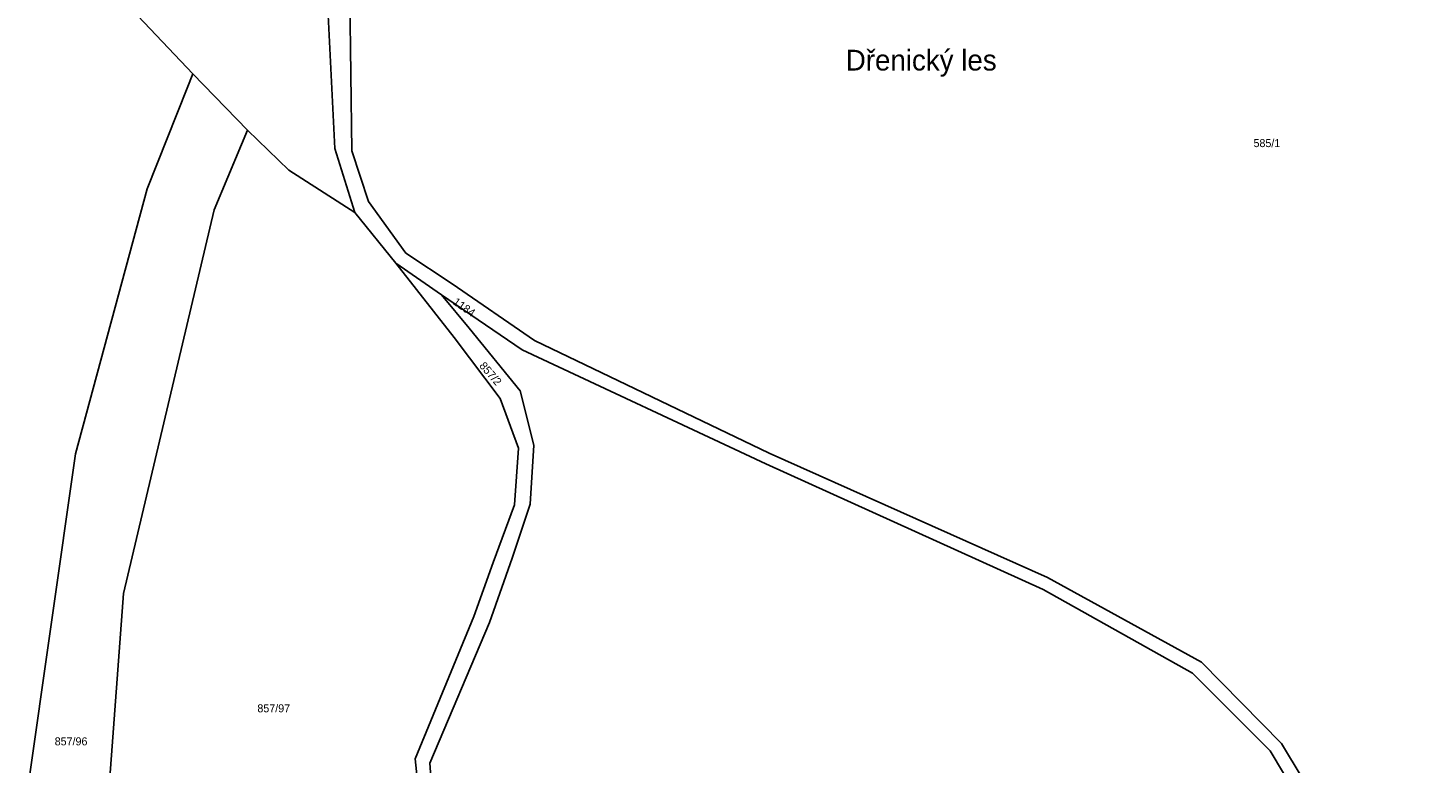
# Model space of a CAD drawing. Extents: x -887272 to -877616, y -1026687 to -1019819.
# Drawn here: x -884977.6 to -884684.7, y -1024492.3 to -1024336 of the extents above; entities that cross this region are included whole.
import ezdxf

# ---------------------------------------------------------------- set-up
doc = ezdxf.new("R2010")
doc.units = 0
for name, color, linetype in [('Hranice parcel', 7, 'Continuous'), ('Parcelní čísla', 7, 'Continuous'), ('Pop  PČ popisy', 7, 'Continuous')]:
    doc.layers.add(name, color=color, linetype=linetype)

msp = doc.modelspace()

# ---------------------------------------------------------------- linework, layer by layer
at = {"layer": 'Hranice parcel'}
for p, q in [((-884942.46, -1024345.79), (-884930.86, -1024357.79)), ((-884908.06, -1024375.26), (-884899.36, -1024386)), ((-884889.62, -1024392.74), (-884899.36, -1024386))]:
    msp.add_line(p, q, dxfattribs=at)
for points in [[(-884867, -1024267.34), (-884875.02, -1024271.26), (-884886.68, -1024276.28), (-884897.76, -1024288.38), (-884904.78, -1024302.7), (-884909.14, -1024329.5), (-884908.7, -1024362.16), (-884905.12, -1024372.96), (-884897.2, -1024383.94), (-884887.36, -1024390.42), (-884869.88, -1024402.44), (-884820.08, -1024426.42), (-884760.96, -1024452.82), (-884728.26, -1024470.78), (-884711.24, -1024488.02), (-884684.7, -1024532.14), (-884687.32, -1024533.72), (-884713.62, -1024489.62), (-884730.14, -1024473.14), (-884761.82, -1024455.36), (-884820.76, -1024428.66), (-884872.5, -1024404.46), (-884889.62, -1024392.74)], [(-884908.06, -1024375.26), (-884912.32, -1024361.66), (-884913.92, -1024329.04), (-884912.02, -1024321.44), (-884907.56, -1024302.44), (-884901.6, -1024290.26)], [(-884931.77, -1024296.62), (-884935.28, -1024300.18), (-884959.34, -1024327.94), (-884942.46, -1024345.79)], [(-884942.46, -1024345.79), (-884943.67, -1024348.85), (-884952.13, -1024370.24), (-884967.4, -1024426.5), (-884977.56, -1024498.03), (-884975.38, -1024556), (-884968.79, -1024626.99)], [(-884954.52, -1024616.8), (-884963.4, -1024540.07), (-884957.22, -1024456.17), (-884937.95, -1024374.67), (-884932.13, -1024360.8), (-884930.86, -1024357.79)], [(-884930.86, -1024357.79), (-884922.1, -1024366.3), (-884908.06, -1024375.26)], [(-884899.36, -1024386), (-884886.98, -1024401.82), (-884877.18, -1024414.78), (-884873.26, -1024425.34), (-884874.16, -1024437.38), (-884878.68, -1024449.62), (-884882.76, -1024461.06), (-884895.24, -1024491.3), (-884893.28, -1024510.06)], [(-884889.62, -1024392.74), (-884883.78, -1024399.82), (-884872.96, -1024413.16), (-884870.02, -1024424.7), (-884870.84, -1024437.22), (-884874.62, -1024448.72), (-884879.48, -1024462.32), (-884892.1, -1024492.2), (-884891.84, -1024496.1)]]:
    msp.add_lwpolyline(points, dxfattribs=at)

# ---------------------------------------------------------------- texts
at = {"layer": 'Parcelní čísla'}
for s, p in [('585/1', (-884717.18, -1024361.38)), ('857/97', (-884928.75, -1024481.43)), ('857/96', (-884971.8, -1024488.45))]:
    msp.add_text(s, height=1.7, dxfattribs=at).set_placement(p)
for s, rotation, p in [('1184', 325, (-884887.38, -1024394.62)), ('857/2', 311, (-884881.73, -1024407.91))]:
    msp.add_text(s, height=1.7, rotation=rotation, dxfattribs=at).set_placement(p)
at = {"layer": 'Pop  PČ popisy'}
msp.add_text('Dřenický les', height=4.4, dxfattribs=at).set_placement((-884803.78, -1024345.11))

doc.saveas('drawing.dxf')
